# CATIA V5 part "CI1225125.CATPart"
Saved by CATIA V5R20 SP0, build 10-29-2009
Part number: CI1225125
Bounding box of the stored display mesh (mm): x -24 to 24, y -20.022 to 159.5, z -27.733 to 28.158
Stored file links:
  C:\Users\Raffaele\Desktop\3D X SITO CF\BOLEX\19-INCLINED ASSEMBLY REF_CI\CI1225125.CATPart

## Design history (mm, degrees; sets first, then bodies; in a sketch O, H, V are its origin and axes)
Set1
  DatumSurface1 to DatumSurface16 "MANIFOLD_SOLID_BREP #389"
  DatumSurface17 to DatumSurface39 "MANIFOLD_SOLID_BREP #1134"
Body1 (main body)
